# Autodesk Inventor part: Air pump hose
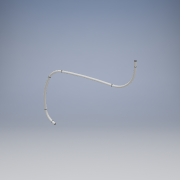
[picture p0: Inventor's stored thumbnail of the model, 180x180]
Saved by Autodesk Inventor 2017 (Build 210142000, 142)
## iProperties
Created: 2020-03
Part Number: Air pump hose
Material: Generic
Document SubType Name: Modeling
Designer: user
Density: 1 g/cm^3
Appearance: Default
Author: user
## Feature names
1. Sweep1
## Parameters: d0 = 342.232 mm, d1 = 32.652 mm, d2 = 0, d5 = 12 mm, d6 = 28.83633 mm, d7 = 6 mm, d8 = 7.2 mm, d9 = 0, d10 = 0
